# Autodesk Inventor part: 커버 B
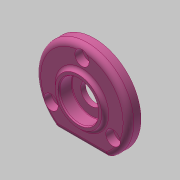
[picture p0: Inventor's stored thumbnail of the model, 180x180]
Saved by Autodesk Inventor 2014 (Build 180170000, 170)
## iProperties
Created: 2020-04
Part Number: 커버 B
Material: 알루미늄 6061
Document SubType Name: Modeling
Designer: mduedu
Density: 2.71 g/cm^3
Appearance: 분홍색
Mass: 33.6775 g
Surface Area: 62.2844 cm^2
Volume: 12.4271 cm^3
Author: mduedu
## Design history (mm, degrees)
sketch "스케치1"
  geometry: C1 r 26 at (0, 0); 1 further point
  constraints: 1 centre point, 1 coincident
  dimensions: "d0" = 52 diameter of C1
extrude "돌출1" new body sketch "스케치1" distance "d1" = 7; taper "d2" = 0 deg
sketch "스케치2"
  geometry: L1 (-14.62, -21.5)-(14.62, -21.5); A1 r 26 centre (0, 0) between (-14.62, -21.5) and (14.62, -21.5) reference; 1 further point
  constraints: 2 end point, 2 point on circle, 1 horizontal
  dimensions: "d3" = 21.5 distance from line of L1 point (0, 0)
extrude "돌출2" cut sketch "스케치2" stored distance "d4" = 7; taper "d5" = 0 deg
sketch "스케치6"
  geometry: C1 r 13 at (0, 0); 1 further point
  constraints: 1 centre point, 1 coincident
  dimensions: "d29" = 26 diameter of C1
extrude "돌출5" join sketch "스케치6" distance "d30" = 2; taper "d31" = 0 deg
fillet "모깎기1" dims "d6" = 3
fillet "모깎기2" dims "d7" = 3
fillet "모깎기4" dims "d33" = 2
sketch "스케치3" dims "d8" = 40
  geometry: 3 further points
  constraints: 2 vertical alignment, 1 coincident, 2 other
hole "구멍1" sketch "스케치3" at (0, 20) diameter "d9" = 4.5; stored, may be unused: countersink angle "d13" = 90 deg, drill point angle "d15" = 118 deg; dims "d10" = 6, "d11" = 8, "d12" = 4.4, "d14" = 8
sketch "스케치4"
  geometry: C1 r 14 at (0, 0); 1 further point
  constraints: 1 centre point, 1 coincident
  dimensions: "d19" = 28 diameter of C1
extrude "돌출3" join sketch "스케치4" distance "d20" = 4; taper "d21" = 0 deg
sketch "스케치5"
  geometry: C1 r 12 at (0, 0); 1 further point
  constraints: 1 centre point, 1 coincident
  dimensions: "d22" = 24 diameter of C1
extrude "돌출4" cut sketch "스케치5" distance "d23" = 3; taper "d24" = 0 deg
fillet "모깎기3" dims "d25" = 3
chamfer "모따기1" distance "d26" = 0.5; stored, may be unused: second distance "d27" = 2, angle "d28" = 45 deg
sketch "스케치7"
  geometry: 2 further points
  constraints: 1 coincident
hole "구멍2" sketch "스케치7" at (0, 0) diameter "d34" = 12; stored, may be unused: countersink angle "d38" = 90 deg, drill point angle "d40" = 118 deg; dims "d35" = 6, "d36" = 22, "d37" = 7.3, "d39" = 8
fillet "모깎기5" dims "d41" = 0.3
chamfer "모따기2" distance "d42" = 0.7; stored, may be unused: second distance "d43" = 2, angle "d44" = 30 deg
node "솔리드1"
pattern_circular "원형 패턴1" dims angle "d17" = 360 deg
node "투영된 루프1"
